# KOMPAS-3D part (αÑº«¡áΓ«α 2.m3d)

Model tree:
1. Эскиз:1
2. Операция выдавливания:36
     Толщина стенки 1 = 2; Толщина стенки 2 = 6; Расстояние 1 = 1; Расстояние 2 = 3
3. Эскиз:38
4. Операция выдавливания:40
     Толщина стенки 1 = 2; Толщина стенки 2 = 6; Расстояние 1 = 5; Расстояние 2 = 3
5. Эскиз:39
6. Операция выдавливания:41
     Толщина стенки 1 = 2; Толщина стенки 2 = 6; Расстояние 1 = 1; Расстояние 2 = 3
7. Эскиз:40
8. Операция выдавливания:42
     Толщина стенки 1 = 2; Толщина стенки 2 = 2.5; Расстояние 1 = 50; Расстояние 2 = 3
9. Эскиз:41
10. Вырезать элемент выдавливания:4
     Толщина стенки 2 = 1.5; Расстояние 1 = 40
11. Эскиз:42
12. Операция выдавливания:43
     Толщина стенки 1 = 2; Толщина стенки 2 = 2.5; Расстояние 1 = 50; Расстояние 2 = 3
13. Эскиз:43
14. Вырезать элемент выдавливания:5
     Толщина стенки 2 = 1.5; Расстояние 1 = 40
15. Эскиз:44
16. Операция выдавливания:44
     Толщина стенки 1 = 2; Толщина стенки 2 = 2.5; Расстояние 1 = 10; Расстояние 2 = 3
17. Эскиз:45
18. Эскиз:46
19. Операция выдавливания:47
     Толщина стенки 1 = 2; Толщина стенки 2 = 6; Расстояние 1 = 1; Расстояние 2 = 3
20. Эскиз:47
21. Операция выдавливания:48
     Толщина стенки 1 = 2; Толщина стенки 2 = 6; Расстояние 1 = 5; Расстояние 2 = 3
22. Эскиз:48
23. Операция выдавливания:49
     Толщина стенки 1 = 2; Толщина стенки 2 = 6; Расстояние 1 = 1; Расстояние 2 = 3
24. Эскиз:49
25. Вырезать элемент выдавливания:6
     Толщина стенки 2 = 1.5; Расстояние 1 = 22
26. Эскиз:50
27. Вырезать элемент выдавливания:7
     Толщина стенки 2 = 1.5; Расстояние 1 = 1
28. Эскиз:51
29. Вырезать элемент выдавливания:8
     Толщина стенки 2 = 1.5; Расстояние 1 = 151
30. Эскиз:52
31. Операция выдавливания:50
     Толщина стенки 1 = 2; Толщина стенки 2 = 6; Расстояние 1 = 1; Расстояние 2 = 0.5
